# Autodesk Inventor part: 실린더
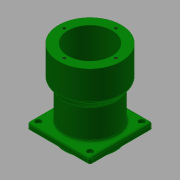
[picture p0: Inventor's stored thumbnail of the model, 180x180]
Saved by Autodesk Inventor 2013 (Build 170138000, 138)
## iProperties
Created: 2016-11
Part Number: 실린더
Material: 알루미늄 6061
Document SubType Name: Modeling
Designer: mduedu
Density: 1 g/cm^3
Author: mduedu
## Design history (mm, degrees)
sketch "스케치1"
  geometry: L1 (0, 0)-(0, 110); L2 (30, 0)-(30, 110); L3 (30, 110)-(42.5, 110); L4 (42.5, 110)-(42.5, 70); L5 (42.5, 70)-(35, 60); L6 (35, 60)-(35, 0); L7 (35, 0)-(30, 0)
  constraints: 14 end point, 4 parallel, 2 horizontal alignment, 1 perpendicular, 1 vertical
  dimensions: "d0" = 110 distance of L1.start L1.end; "d1" = 60 diameter of L2.end L1; "d2" = 85 diameter of L3.end L1; "d3" = 70 diameter of L6.end L1; "d4" = 40 distance of L3.end L4.end; "d5" = 50 vertical distance of L5.end L3.end
revolve "회전1" sketch "스케치1" stored, may be unused: angle "d6" = 90 deg
node "작업 평면1"
sketch "스케치2"
  geometry: L1 (-42.5, -42.5)-(42.5, -42.5); L2 (42.5, -42.5)-(42.5, 42.5); L3 (42.5, 42.5)-(-42.5, 42.5); L4 (-42.5, 42.5)-(-42.5, -42.5); L5 (-42.5, -42.5)-(42.5, 42.5); L6 (42.5, -42.5)-(-42.5, 42.5); C1 r 35 at (0, 0) reference; C2 r 35 at (0, 0); 1 further point
  constraints: 12 end point, 2 midpoint, 2 parallel, 2 perpendicular, 1 centre point, 1 coincident, 1 concentric, 1 horizontal
  dimensions: "d8" = 85 distance of L2.end L3.end
extrude "돌출1" join sketch "스케치2" distance "d10" = 8; taper "d11" = 0 deg
fillet "모깎기1" dims "d12" = 3
fillet "모깎기2" dims "d13" = 3
chamfer "모따기1" distance "d14" = 1; stored, may be unused: second distance "d15" = 2, angle "d16" = 45 deg
chamfer "모따기2" distance "d17" = 5; stored, may be unused: second distance "d18" = 2, angle "d19" = 15 deg
sketch "스케치3"
  geometry: L1 (-35, -35)-(35, -35); L2 (35, -35)-(35, 35); L3 (35, 35)-(-35, 35); L4 (-35, 35)-(-35, -35); L5 (-35, -35)-(35, 35); L6 (35, -35)-(-35, 35); 5 further points
  constraints: 12 end point, 4 coincident, 2 midpoint, 2 parallel, 1 horizontal, 1 perpendicular
  dimensions: "d20" = 70 distance of L3.end L2.end; "d21" = 70 distance of L2.end L1.end
sketch "스케치4"
  geometry: 4 further points
  constraints: 4 other
hole "구멍1" sketch "스케치4" at (-35, 35), (35, 35), (35, -35), (-35, -35) diameter "d22" = 4.5; stored, may be unused: countersink angle "d26" = 90 deg, drill point angle "d28" = 0 deg; dims "d23" = 6, "d24" = 8, "d25" = 4.6, "d27" = 8
sketch "스케치5"
  geometry: 4 further points
  constraints: 4 other
hole "구멍2" sketch "스케치5" at (0, -35), (35, 0), (-35, 0), (0, 35) diameter "d29" = 4.134; stored, may be unused: countersink angle "d33" = 90 deg, drill point angle "d35" = 120 deg; dims "d30" = 7.5, "d31" = 4, "d32" = 2, "d34" = 10
node "솔리드1"
